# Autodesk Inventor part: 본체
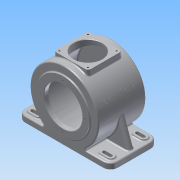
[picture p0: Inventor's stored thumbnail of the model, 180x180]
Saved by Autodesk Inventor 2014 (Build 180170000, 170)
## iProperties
Created: 2015-06
Part Number: 본체
Material: 알루미늄 6061
Document SubType Name: Modeling
Designer: 학생용
Density: 2.71 g/cm^3
Appearance: 알루미늄 - 평지
Mass: 3275.33 g
Surface Area: 2299.7 cm^2
Volume: 1208.61 cm^3
Author: 학생용
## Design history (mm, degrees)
sketch "스케치1"
  geometry: L1 (-115, -59)-(115, -59); L2 (115, -59)-(115, 59); L3 (115, 59)-(-115, 59); L4 (-115, 59)-(-115, -59); L5 (-115, -59)-(115, 59); L6 (115, -59)-(-115, 59); 3 further points
  constraints: 12 end point, 3 midpoint, 2 parallel, 1 coincident, 1 horizontal, 1 perpendicular
  dimensions: "d1" = 230 distance of L2.end L3.end; "d2" = 118 distance of L3.end L1.start
extrude "돌출1" new body sketch "스케치1" distance "d3" = 14; taper "d4" = 0 deg
sketch "스케치2"
  geometry: L1 (0, 0)-(230, 0) reference; C1 r 85 at (115, 85); 2 further points
  constraints: 1 centre point, 1 midpoint, 1 vertical alignment
  dimensions: "d5" = 85 distance of point (115, 0) C1.centre; "d6" = 170 diameter of C1
extrude "돌출2" join sketch "스케치2" distance "d7" = 118; taper "d8" = 0 deg
sketch "스케치3"
  geometry: L1 (0, 0)-(230, 0) reference; C1 r 65 at (115, 85); 2 further points
  constraints: 1 centre point, 1 midpoint, 1 vertical alignment
  dimensions: "d9" = 130 diameter of C1; "d32" = 85 distance of point (115, 0) C1.centre
extrude "돌출3" join sketch "스케치3" distance "d10" = 3; taper "d11" = 0 deg
sketch "스케치4"
  geometry: C1 r 65 at (115, -85); 1 further point
  constraints: 1 centre point
  dimensions: "d12" = 130 diameter of C1
extrude "돌출4" join sketch "스케치4" distance "d13" = 13; taper "d14" = 0 deg
node "작업 평면1"
sketch "스케치5"
  geometry: C1 r 77 at (115, 85); A1 r 85 centre (115, 85) between (161.733, 14) and (68.267, 14) reference; 1 further point
  constraints: 1 centre point
  dimensions: "d16" = 154 diameter of C1
extrude "돌출5" cut sketch "스케치5" distance "d17" = 102; taper "d18" = 0 deg
sketch "스케치6"
  geometry: C1 r 47.5 at (0, 0); 1 further point
  constraints: 1 centre point
  dimensions: "d19" = 95 diameter of C1
extrude "돌출6" cut sketch "스케치6" stored distance "d20" = 102; taper "d21" = 0 deg
sketch "스케치7"
  geometry: C1 r 31 at (0, 0); 1 further point
  constraints: 1 centre point
  dimensions: "d22" = 62 diameter of C1
extrude "돌출7" join sketch "스케치7" distance "d23" = 3.5; taper "d24" = -25 deg
sketch "스케치8"
  geometry: C1 r 23.5 at (0, 0); 1 further point
  constraints: 1 centre point
  dimensions: "d25" = 47 diameter of C1
extrude "돌출8" cut sketch "스케치8" distance "d26" = 14; taper "d27" = 0 deg
sketch "스케치9"
  geometry: C1 r 23.5 at (0, 0) reference; C2 r 15 at (0, 0); 1 further point
  constraints: 2 coincident, 1 centre point
  dimensions: "d29" = 30 diameter of C2
extrude "돌출9" cut sketch "스케치9" distance "d30" = 3; taper "d31" = 0 deg
node "작업 평면2"
sketch "스케치10"
  geometry: L1 (42.5, 42.5)-(-42.5, 42.5); L2 (-42.5, 42.5)-(-42.5, -42.5); L3 (-42.5, -42.5)-(42.5, -42.5); L4 (42.5, -42.5)-(42.5, 42.5); 3 further points
  constraints: 8 end point, 2 midpoint, 2 parallel, 2 perpendicular, 1 horizontal, 1 horizontal alignment, 1 vertical alignment
  dimensions: "d34" = 85 distance of L1.start L1.end
extrude "돌출10" join sketch "스케치10" stored distance "d35" = 3; taper "d36" = 0 deg
sketch "스케치11"
  geometry: C1 r 35 at (0, 0); 1 further point
  constraints: 1 centre point, 1 coincident
  dimensions: "d37" = 70 diameter of C1
extrude "돌출11" cut sketch "스케치11" stored distance "d38" = 3; taper "d39" = 0 deg
node "작업 평면3"
sketch "스케치12"
  geometry: L1 (0, 0)-(0, 14) reference; L2 (68.267, 14)-(0, 14) reference; L3 (6, 14)-(30.13, 80.297); A1 r 85 centre (115, 85) between (161.733, 14) and (68.267, 14) reference; 1 further point
  constraints: 2 end point, 1 point on circle, 1 point on line
  dimensions: "d41" = 6 distance of L1.end L3.start; "d42" = 110 deg angle of L2 L3
feature "리브1" sketch "스케치12" dims "d43" = 1, "d44" = 15, "d45" = 0, "d46" = 0, "d47" = 1, "d48" = 1
sketch "스케치13"
  geometry: L1 (-97, -50)-(-81, -50); L2 (-97, -32)-(-81, -32); A1 r 9 centre (-97, -41) between (-97, -32) and (-97, -50); A2 r 9 centre (-81, -41) between (-81, -50) and (-81, -32); 1 further point
  constraints: 4 end point, 4 point on circle, 4 tangent, 2 centre point, 1 horizontal alignment
  dimensions: "d50" = 16 distance of A2.centre A1.centre; "d52" = 18 distance between parallel lines of L1 L2; "d53" = 41 vertical distance of point (0, 0) A1.centre; "d54" = 97 horizontal distance of point (0, 0) A1.centre
extrude "돌출12" join sketch "스케치13" distance "d55" = 3; taper "d56" = 0 deg
sketch "스케치14"
  geometry: L1 (-97, -50)-(-81, -50) reference; L2 (-81, -32)-(-97, -32) reference; L3 (-81, -45)-(-97, -45); L4 (-97, -37)-(-81, -37); A1 r 9 centre (-81, -41) between (-81, -50) and (-81, -32) reference; A2 r 9 centre (-97, -41) between (-97, -32) and (-97, -50) reference; A3 r 4 centre (-81, -41) between (-81, -45) and (-81, -37); A4 r 4 centre (-97, -41) between (-97, -37) and (-97, -45); 1 further point
  constraints: 4 end point, 4 point on circle, 2 centre point, 3 other
  dimensions: "d57" = 8 distance between parallel lines of L3 L4
extrude "돌출13" cut sketch "스케치14" stored distance "d58" = 3; taper "d59" = 0 deg
sketch "스케치15"
  geometry: L1 (0, 85)-(-77.036, 120.923); L2 (0, 85)-(-84.995, 85) reference; A1 r 85 centre (0, 85) between (46.733, 14) and (-46.733, 14) reference; 2 further points
  constraints: 4 end point, 1 horizontal
  dimensions: "d60" = 25 deg angle of L2 L1
node "작업 평면4"
sketch "스케치16"
  geometry: 3 further points
  constraints: 2 coincident, 2 other
feature "엠보싱1" sketch "스케치16" dims "d61" = 0.5, "d62" = 0
fillet "모깎기1" dims "d63" = 0.3
fillet "모깎기2" dims "d64" = 18
fillet "모깎기3" dims "d65" = 7
fillet "모깎기4" dims "d66" = 7.5
fillet "모깎기5" dims "d67" = 3
fillet "모깎기6" dims "d68" = 3
fillet "모깎기7" dims "d69" = 3
chamfer "모따기1" distance "d70" = 1; stored, may be unused: second distance "d71" = 2, angle "d72" = 45 deg
sketch "스케치17"
  geometry: A1 r 7 centre (-35.5, -35.5) between (-42.5, -35.5) and (-35.5, -42.5) reference; A2 r 7 centre (35.5, -35.5) between (35.5, -42.5) and (42.5, -35.5) reference; A3 r 7 centre (35.5, 35.5) between (42.5, 35.5) and (35.5, 42.5) reference; A4 r 7 centre (-35.5, 35.5) between (-35.5, 42.5) and (-42.5, 35.5) reference
hole "구멍1" sketch "스케치17" at (-35.5, 35.5), (35.5, 35.5), (35.5, -35.5), (-35.5, -35.5) diameter "d73" = 3.459; stored, may be unused: countersink angle "d77" = 90 deg, drill point angle "d79" = 118 deg; dims "d74" = 10, "d75" = 4, "d76" = 2, "d78" = 13
fillet "모깎기8" dims "d91" = 3
sketch "스케치19"
  geometry: C1 r 65 at (0, 0) reference; C2 r 55 at (0, 0); 2 further points
  constraints: 1 centre point, 1 coincident
  dimensions: "d93" = 110 diameter of C2
hole "구멍3" sketch "스케치19" at (0, 54.998) diameter "d94" = 3.459; stored, may be unused: countersink angle "d98" = 90 deg, drill point angle "d100" = 118 deg; dims "d95" = 20, "d96" = 4, "d97" = 2, "d99" = 13
node "솔리드1"
mirror "대칭1"
mirror "대칭2"
mirror "대칭3"
pattern_circular "원형 패턴2" dims angle "d102" = 360 deg
other parameters: "d15" = -8, "d33" = -173, "d40" = -59, "d51" = 18
